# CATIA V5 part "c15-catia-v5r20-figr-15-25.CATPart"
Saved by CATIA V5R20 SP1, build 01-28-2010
Part number: Part1
Bounding box of the stored display mesh (mm): x -50 to 50, y -25 to 26, z -24 to 1
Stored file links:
  D:\v5_r20\psrt_files_downloaded\c15\c15-catia-v5r20-figr-15-25.CATPart
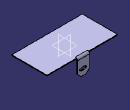
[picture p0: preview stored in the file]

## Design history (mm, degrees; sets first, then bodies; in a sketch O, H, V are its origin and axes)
SheetMetalParameters1: Thickness 1, BendRadius 2, KFactor 0.400515 {= log(min(100,max(20*SheetMetalParameters1.BendRadius,SheetMetalParameters1.Thickness)/SheetMetalParameters1.Thickness))/log(100)/2}, ReliefRadialLength 1, ReliefAxialLength 2, MinimumBendRadius 0
Body1 (main body)
  Sketch1 on xy-plane, origin (0, 0, 0), H (1, 0, 0), V (0, 1, 0)
    line L1 (-50, 25) -> (50, 25)
    line L2 (50, 25) -> (50, -25)
    line L3 (50, -25) -> (-50, -25)
    line L4 (-50, -25) -> (-50, 25)
    length L1 = 100
    distance V L2 = 50
    length L2 = 50
    distance H L3 = 25
    horizontal: L1 H, L3 H
    vertical: L2 V, L4 V
  Wall1: Thickness 1, Profile Sketch1
  Sketch2 on face of Wall1, origin (50, 25, 0), H (-1, 0, 0), V (0, 0, 1)
    line L1 (42.3549, 1) -> (42.3549, -19)
    point P2 (42.3549, -19)
    line L2 (42.3549, -19) -> (47.3549, -24)
    point P3 (47.3549, -24)
    line L3 (47.3549, -24) -> (54.3549, -24)
    point P4 (54.3549, -24)
    line L4 (54.3549, -24) -> (59.3549, -19)
    point P5 (59.3549, -19)
    line L5 (59.3549, -19) -> (59.3549, 1)
    line L6 (59.3549, 1) -> (42.3549, 1)
    reference projected line E1 (100, 1) -> (0, 1) from edge [face of Wall1 | face of Wall1]
    ellipse A1 centre (50.1164, -15.2153) semi-axes 5.0583, 2.1402 rotation 0
    length L5 = 20
    length L1 = 20
    length L3 = 7
    distance P4 L5 = 5
    distance P2 P3 H = 5
    distance L3 P5 = 5
    vertical: L1 V, L5 V
    horizontal: L3 H, L6 H
    coincidence: L6 E1
    parallelism: A1 L3
  d_NewWallOnEdge1: NewWallOnEdge_Edge edge [face of Wall1 | face of Wall1], NewWallOnEdge_WallProfile Sketch2, NewWallOnEdge_Length 100, NewWallOnEdge_HeightLimitOffset 0, NewWallOnEdge_WidthOffset1 0, NewWallOnEdge_WidthOffset2 0, NewWallOnEdge_Angle 0, NewWallOnEdge_BendRadiusValue 2 {= SheetMetalParameters1.BendRadius}, NewWallOnEdge_BendTable SheetMetalParameters1, KFacteur 0.400515 {= log(min(100,max(20*d_NewWallOnEdge1.Radius,SheetMetalParameters1.Thickness)/SheetMetalParameters1.Thickness))/log(100)/2}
